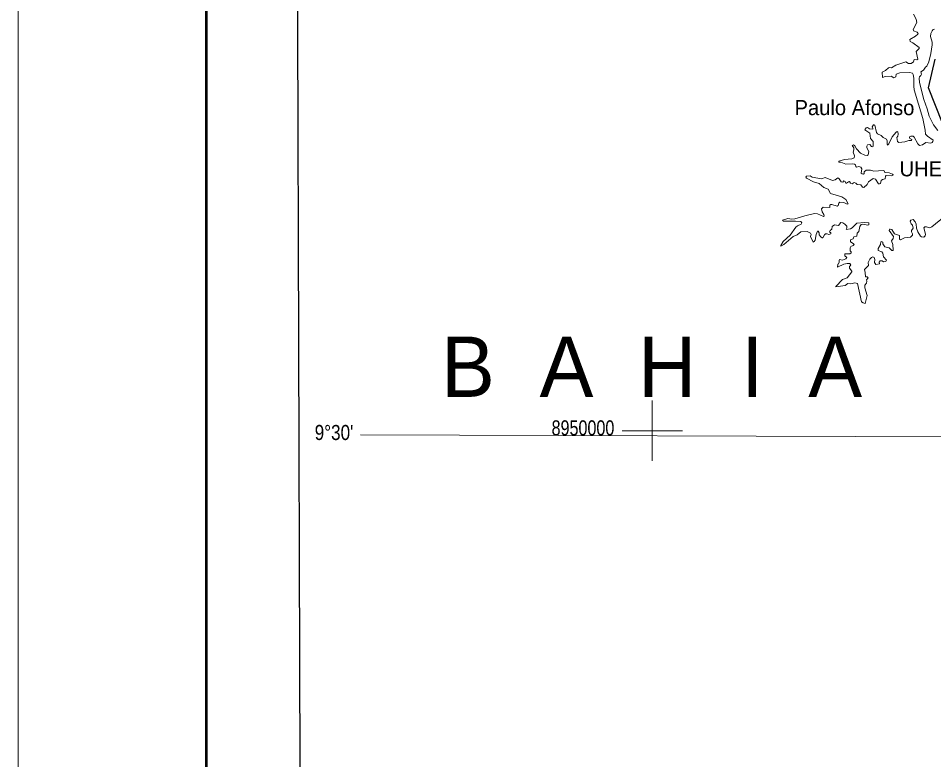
# Model space of a CAD drawing. Extents: x 553962 to 842807, y 8883888 to 9032388.
# Drawn here: x 553962 to 584337, y 8939083 to 8963682 of the extents above; entities that cross this region are included whole.
import ezdxf
from ezdxf.enums import TextEntityAlignment as Align

# ---------------------------------------------------------------- set-up
doc = ezdxf.new("R2010")
doc.units = 0
doc.header["$LTSCALE"] = 150
for name, color, linetype, lineweight in [('1', 7, 'Continuous', 13), ('2', 7, 'Continuous', 13), ('21', 7, 'Continuous', 25), ('25', 7, 'Continuous', 13), ('3', 7, 'Continuous', 13)]:
    doc.layers.add(name, color=color, linetype=linetype, lineweight=lineweight)
for name, color, linetype in [('41', 7, 'Continuous'), ('42', 7, 'Continuous'), ('46', 7, 'Continuous'), ('47', 7, 'Continuous')]:
    doc.layers.add(name, color=color, linetype=linetype)

msp = doc.modelspace()

# ---------------------------------------------------------------- linework, layer by layer
at = {"layer": '1'}
msp.add_line((565315.3, 8949866.8), (791497.7, 8949052.2), dxfattribs=at)
at = {"layer": '2'}
for p, q in [((575000, 8949000), (575000, 8951000)), ((574000, 8950000), (576000, 8950000))]:
    msp.add_line(p, q, dxfattribs=at)
at = {"layer": '21'}
msp.add_lwpolyline([(584626.8, 8960201.4), (584162.8, 8961372.1), (584384.7, 8962320.7)], dxfattribs=at)
at = {"layer": '25'}
for points in [[(582299.4, 8960082.5), (582339.6, 8960143.8), (582362.8, 8960152.2), (582381.9, 8960139.6), (582443.6, 8959893.3), (582477.6, 8959853), (582596.3, 8959797.7), (582656.1, 8959725.5), (582771.8, 8959670.2), (582795.6, 8959619.4), (582792, 8959510.9), (582809, 8959470.7), (582851.4, 8959515.1), (582957.8, 8959753.2), (583089.5, 8959901.9), (583125.3, 8959922.9), (583148.8, 8959914.2), (583159.4, 8959833.8), (583144.6, 8959774.5), (583108.6, 8959723.3), (583108.6, 8959723.3), (583138.3, 8959595.9), (583184.5, 8959559.9), (583382, 8959578.8), (583514.4, 8959627.7), (583603.4, 8959628), (583607.5, 8959661.8), (583550.2, 8959691.6), (583531.3, 8959731.8), (583541.6, 8959757), (583580.3, 8959774.3), (583651.7, 8959765.9), (583684, 8959740.2), (583809.5, 8959521.5), (583862.6, 8959466.3), (583962.4, 8959487.6), (584070.6, 8959557.6), (584244.7, 8959542.8), (584281, 8959557.7), (584312.8, 8959595.8), (584315, 8959638.2), (584126, 8959774.3), (584064.3, 8959836.4), (584055.9, 8959969.5), (583979.3, 8960356.6), (583690.5, 8961308.2), (583675.7, 8961427), (583679.9, 8961694.8), (583656.7, 8961812.9), (583631.9, 8961861.4), (583535.2, 8961883.6), (583208.6, 8961873.1), (583093.8, 8961826.3), (583082.9, 8961741.4), (583013.1, 8961707.5), (582923.6, 8961760.4), (582724.2, 8961752), (582642.1, 8961718.4), (582632.6, 8961889.8), (582741.2, 8961953.9), (582832.4, 8962038.7), (582866.3, 8962051.4), (582940.9, 8962038.9), (583076.4, 8962125.7), (583410.3, 8962234), (583497.2, 8962176.9), (583584.3, 8962176.9), (583662.8, 8962238.5), (583692.8, 8962310.5), (583781.6, 8962306.4), (583807.2, 8962323.5), (583752.2, 8962580.2), (583853.2, 8962685.6), (583854, 8962716.3), (583639.8, 8962873.4), (583552.7, 8962911.8), (583548.2, 8962977.4), (583737.5, 8963086.2), (583815.2, 8963159.7), (583820, 8963181), (583784.2, 8963226), (583667.3, 8963264.5), (583654.7, 8963312.4), (583773.3, 8963547.2), (583756.3, 8963657.4), (583667.3, 8963822.9)], [(582299.4, 8960082.5), (582339.6, 8960143.8), (582362.8, 8960152.2), (582381.9, 8960139.6), (582443.6, 8959893.3), (582477.6, 8959853), (582596.3, 8959797.7), (582656.1, 8959725.5), (582771.8, 8959670.2), (582795.6, 8959619.4), (582792, 8959510.9), (582809, 8959470.7), (582851.4, 8959515.1), (582957.8, 8959753.2), (583089.5, 8959901.9), (583125.3, 8959922.9), (583148.8, 8959914.2), (583159.4, 8959833.8), (583144.6, 8959774.5), (583108.6, 8959723.3), (583108.6, 8959723.3), (583138.3, 8959595.9), (583184.5, 8959559.9), (583382, 8959578.8), (583514.4, 8959627.7), (583603.4, 8959628), (583607.5, 8959661.8), (583550.2, 8959691.6), (583531.3, 8959731.8), (583541.6, 8959757), (583580.3, 8959774.3), (583651.7, 8959765.9), (583684, 8959740.2), (583809.5, 8959521.5), (583862.6, 8959466.3), (583962.4, 8959487.6), (584070.6, 8959557.6), (584244.7, 8959542.8), (584281, 8959557.7), (584312.8, 8959595.8), (584315, 8959638.2), (584126, 8959774.3), (584064.3, 8959836.4), (584055.9, 8959969.5), (583979.3, 8960356.6), (583690.5, 8961308.2), (583675.7, 8961427), (583679.9, 8961694.8), (583656.7, 8961812.9), (583631.9, 8961861.4), (583535.2, 8961883.6), (583208.6, 8961873.1), (583093.8, 8961826.3), (583082.9, 8961741.4), (583013.1, 8961707.5), (582923.6, 8961760.4), (582724.2, 8961752), (582642.1, 8961718.4), (582632.6, 8961889.8), (582741.2, 8961953.9), (582832.4, 8962038.7), (582866.3, 8962051.4), (582940.9, 8962038.9), (583076.4, 8962125.7), (583410.3, 8962234), (583497.2, 8962176.9), (583584.3, 8962176.9), (583662.8, 8962238.5), (583692.8, 8962310.5), (583781.6, 8962306.4), (583807.2, 8962323.5), (583752.2, 8962580.2), (583853.2, 8962685.6), (583854, 8962716.3), (583639.8, 8962873.4), (583552.7, 8962911.8), (583548.2, 8962977.4), (583737.5, 8963086.2), (583815.2, 8963159.7), (583820, 8963181), (583784.2, 8963226), (583667.3, 8963264.5), (583654.7, 8963312.4), (583773.3, 8963547.2), (583756.3, 8963657.4), (583667.3, 8963822.9)], [(584367.9, 8963323.8), (584319.4, 8963311.1), (584283.8, 8963267.3), (584244.9, 8963172.8), (584232.2, 8963079.6), (584283.2, 8962892.7), (584283.2, 8962799.2), (584240.7, 8962518.8), (584172.1, 8962236.3), (584113.2, 8962091.9), (584066.4, 8962055.5), (584002.7, 8961956), (583913.8, 8961907.2), (583936.8, 8961830.6), (583913.5, 8961781.7), (583866.6, 8961740.8), (583856.2, 8961694.6), (583869, 8961554.4), (584009.2, 8960993.4), (584121.2, 8960674.7), (584187.7, 8960432.6), (584325.6, 8960152.6), (584476.5, 8959954.9)], [(584367.9, 8963323.8), (584319.4, 8963311.1), (584283.8, 8963267.3), (584244.9, 8963172.8), (584232.2, 8963079.6), (584283.2, 8962892.7), (584283.2, 8962799.2), (584240.7, 8962518.8), (584172.1, 8962236.3), (584113.2, 8962091.9), (584066.4, 8962055.5), (584002.7, 8961956), (583913.8, 8961907.2), (583936.8, 8961830.6), (583913.5, 8961781.7), (583866.6, 8961740.8), (583856.2, 8961694.6), (583869, 8961554.4), (584009.2, 8960993.4), (584121.2, 8960674.7), (584187.7, 8960432.6), (584325.6, 8960152.6), (584476.5, 8959954.9)], [(580099.6, 8958407.9), (580098.5, 8958410.3), (580113.2, 8958444.3), (580235.9, 8958453.9), (580303, 8958410.4), (580612.5, 8958359.6), (580740.2, 8958401.9), (580973.9, 8958304.4), (581064.7, 8958323.4), (581156.5, 8958384.9), (581203.2, 8958359.3), (581270.9, 8958257.8), (581319.8, 8958245), (581360.2, 8958291.4), (581400.5, 8958268.1), (581420.4, 8958210.8), (581447.3, 8958208.8), (581504.7, 8958259.6), (581539.6, 8958263.8), (581539.6, 8958263.8), (581578.9, 8958209), (581627.9, 8958191.9), (581696, 8958236.1), (581748.9, 8958212.8), (581799.4, 8958164.3), (581920, 8958154), (581978.5, 8958081.4), (582019.4, 8958072.8), (582127.2, 8958170.8), (582178.1, 8958253.3), (582332.9, 8958361.5), (582401, 8958344.6), (582505.1, 8958189.8), (582543.4, 8958185.4), (582568.8, 8958204.3), (582596.6, 8958300), (582641.2, 8958331.9), (582721.7, 8958357.6), (582732.5, 8958448.5), (582755.7, 8958467.7), (582953.2, 8958455.2), (582983.1, 8958470.1), (582989.4, 8958491.2), (582974.4, 8958510.4), (582859.9, 8958554.9), (582719.7, 8958570.1), (582696.2, 8958625.2), (582656.2, 8958635.6), (582353.6, 8958614.5), (582235.7, 8958646.3), (582095.5, 8958639.9), (582031.7, 8958591.2), (582027, 8958531.6), (582005.7, 8958514.7), (581967.3, 8958516.9), (581933.7, 8958544.9), (581955, 8958692.5), (581922.9, 8958748.3), (581848.8, 8958761), (581780.6, 8958746.3), (581757.5, 8958761.1), (581738.2, 8958822.6), (581712.6, 8958841.7), (581627.9, 8958854.5), (581424.2, 8958839.7), (581251.8, 8958907.5), (581194.6, 8958907.9), (581190.6, 8958937.3), (581381.2, 8958994.6), (581615.1, 8959015.9), (581699.9, 8959047.7), (581708.6, 8959122.1), (581659.8, 8959239), (581692.1, 8959315.5), (581691.6, 8959378.9), (581634.5, 8959460), (581670.4, 8959485.2), (581717.2, 8959451.2), (581774.6, 8959353.5), (581908.3, 8959202.9), (582046.5, 8959141.3), (582129.4, 8959128.6), (582167.3, 8959147.5), (582188.6, 8959260.2), (582118.7, 8959385.4), (582116.5, 8959440.5), (582142.1, 8959487.4), (582214.1, 8959495.9), (582278, 8959423.9), (582316.1, 8959415.5), (582331, 8959439.1), (582330.8, 8959589.7), (582237.6, 8959695.7), (582220.4, 8959865.6), (582050.7, 8959980.4), (582091.2, 8960052.6), (582141.7, 8960063.2), (582208.1, 8960016.5), (582315.9, 8960001.7), (582322.5, 8960029), (582299.4, 8960082.5)], [(580099.6, 8958407.9), (580098.5, 8958410.3), (580113.2, 8958444.3), (580235.9, 8958453.9), (580303, 8958410.4), (580612.5, 8958359.6), (580740.2, 8958401.9), (580973.9, 8958304.4), (581064.7, 8958323.4), (581156.5, 8958384.9), (581203.2, 8958359.3), (581270.9, 8958257.8), (581319.8, 8958245), (581360.2, 8958291.4), (581400.5, 8958268.1), (581420.4, 8958210.8), (581447.3, 8958208.8), (581504.7, 8958259.6), (581539.6, 8958263.8), (581539.6, 8958263.8), (581578.9, 8958209), (581627.9, 8958191.9), (581696, 8958236.1), (581748.9, 8958212.8), (581799.4, 8958164.3), (581920, 8958154), (581978.5, 8958081.4), (582019.4, 8958072.8), (582127.2, 8958170.8), (582178.1, 8958253.3), (582332.9, 8958361.5), (582401, 8958344.6), (582505.1, 8958189.8), (582543.4, 8958185.4), (582568.8, 8958204.3), (582596.6, 8958300), (582641.2, 8958331.9), (582721.7, 8958357.6), (582732.5, 8958448.5), (582755.7, 8958467.7), (582953.2, 8958455.2), (582983.1, 8958470.1), (582989.4, 8958491.2), (582974.4, 8958510.4), (582859.9, 8958554.9), (582719.7, 8958570.1), (582696.2, 8958625.2), (582656.2, 8958635.6), (582353.6, 8958614.5), (582235.7, 8958646.3), (582095.5, 8958639.9), (582031.7, 8958591.2), (582027, 8958531.6), (582005.7, 8958514.7), (581967.3, 8958516.9), (581933.7, 8958544.9), (581955, 8958692.5), (581922.9, 8958748.3), (581848.8, 8958761), (581780.6, 8958746.3), (581757.5, 8958761.1), (581738.2, 8958822.6), (581712.6, 8958841.7), (581627.9, 8958854.5), (581424.2, 8958839.7), (581251.8, 8958907.5), (581194.6, 8958907.9), (581190.6, 8958937.3), (581381.2, 8958994.6), (581615.1, 8959015.9), (581699.9, 8959047.7), (581708.6, 8959122.1), (581659.8, 8959239), (581692.1, 8959315.5), (581691.6, 8959378.9), (581634.5, 8959460), (581670.4, 8959485.2), (581717.2, 8959451.2), (581774.6, 8959353.5), (581908.3, 8959202.9), (582046.5, 8959141.3), (582129.4, 8959128.6), (582167.3, 8959147.5), (582188.6, 8959260.2), (582118.7, 8959385.4), (582116.5, 8959440.5), (582142.1, 8959487.4), (582214.1, 8959495.9), (582278, 8959423.9), (582316.1, 8959415.5), (582331, 8959439.1), (582330.8, 8959589.7), (582237.6, 8959695.7), (582220.4, 8959865.6), (582050.7, 8959980.4), (582091.2, 8960052.6), (582141.7, 8960063.2), (582208.1, 8960016.5), (582315.9, 8960001.7), (582322.5, 8960029), (582299.4, 8960082.5)], [(579330.4, 8956970.9), (579320.1, 8956982.2), (579494.9, 8957040.3), (579635.1, 8957021.3), (579729, 8957025.6), (580056.8, 8957131.9), (580383.3, 8957210.3), (580477.4, 8957190.9), (580682.8, 8957104.2), (580701.6, 8957122.8), (580693.2, 8957169.7), (580640, 8957259.4), (580619.2, 8957363.6), (580667.8, 8957416.2), (580886.3, 8957410), (580890.9, 8957486.6), (580919.1, 8957507.7), (580955.2, 8957509.6), (581130.8, 8957450.5), (581162.8, 8957476.1), (581188.5, 8957544.2), (581224.5, 8957577.8), (581357.9, 8957571.4), (581466.2, 8957520.6), (581496, 8957526.9), (581421.8, 8957673.3), (581289.9, 8957760.6), (580910.1, 8957870.9), (580835.5, 8958013.2), (580692.5, 8958073.2), (580540.2, 8958198), (580349.1, 8958255.5), (580111.4, 8958382.8), (580099.6, 8958407.9)], [(579330.4, 8956970.9), (579320.1, 8956982.2), (579494.9, 8957040.3), (579635.1, 8957021.3), (579729, 8957025.6), (580056.8, 8957131.9), (580383.3, 8957210.3), (580477.4, 8957190.9), (580682.8, 8957104.2), (580701.6, 8957122.8), (580693.2, 8957169.7), (580640, 8957259.4), (580619.2, 8957363.6), (580667.8, 8957416.2), (580886.3, 8957410), (580890.9, 8957486.6), (580919.1, 8957507.7), (580955.2, 8957509.6), (581130.8, 8957450.5), (581162.8, 8957476.1), (581188.5, 8957544.2), (581224.5, 8957577.8), (581357.9, 8957571.4), (581466.2, 8957520.6), (581496, 8957526.9), (581421.8, 8957673.3), (581289.9, 8957760.6), (580910.1, 8957870.9), (580835.5, 8958013.2), (580692.5, 8958073.2), (580540.2, 8958198), (580349.1, 8958255.5), (580111.4, 8958382.8), (580099.6, 8958407.9)], [(584696, 8957104.7), (584274.9, 8956764.4), (584197.5, 8956726), (584094.1, 8956768.4), (584038.7, 8956757.6), (584011.4, 8956727.3), (584062.2, 8956515.4), (584055.8, 8956462.4), (584011.2, 8956420.2), (583928.7, 8956432.8), (583896.6, 8956454.1), (583805.3, 8956596.4), (583767, 8956723.9), (583756.3, 8956851.3), (583724.4, 8956925.6), (583660.8, 8957002.1), (583580.2, 8956987.2), (583561.1, 8956946.9), (583586.5, 8956859.9), (583628.7, 8956817.4), (583660.7, 8956715.7), (583603.4, 8956642.9), (583599.3, 8956600.4), (583635.2, 8956528.2), (583628.9, 8956482), (583569.2, 8956422.2), (583365.5, 8956403), (583235.8, 8956333.2), (583204.2, 8956354.3), (583197.6, 8956473.1), (583036.3, 8956532.7), (582944.7, 8956675), (582889.9, 8956689.8), (582866.4, 8956681.3), (582857.8, 8956639.1), (583000.1, 8956445.4), (583000.1, 8956445.4), (582995.8, 8956371.3), (582932.2, 8956297.6), (582978.9, 8956171.6), (582991.4, 8955993), (582976.7, 8955976.2), (582947.1, 8955976.2), (582856.3, 8956071.3), (582711.3, 8956099.4), (582652.2, 8956196.2), (582645.2, 8956252.4), (582607.4, 8956273.4), (582579.8, 8956265), (582570.9, 8956175.6), (582492.5, 8956044.1), (582498.8, 8955974.4), (582613.2, 8955937.9), (582649.7, 8955884.6), (582675.3, 8955763.5), (582766.3, 8955661.9), (582751.6, 8955613.2), (582671.6, 8955604.4), (582632.4, 8955638.4), (582558.3, 8955632), (582532.9, 8955594), (582534.7, 8955540.7), (582411.8, 8955511), (582367.2, 8955576.8), (582379.8, 8955678.5), (582358.6, 8955744.6), (582321.7, 8955763.6), (582269.6, 8955750.9), (582214, 8955691.2), (582157.1, 8955581.8), (582171.5, 8955478.9), (582040.1, 8955351.6), (582061.2, 8955249.4), (582072.2, 8955107.3), (582129.2, 8955100.8), (582163, 8955071.2), (582108.2, 8955005.5), (582120.6, 8954960.7), (582103.7, 8954893.1), (582052.8, 8954828.8), (582057, 8954744.1), (582129.2, 8954489.4), (582066.7, 8954223.6)], [(584696, 8957104.7), (584274.9, 8956764.4), (584197.5, 8956726), (584094.1, 8956768.4), (584038.7, 8956757.6), (584011.4, 8956727.3), (584062.2, 8956515.4), (584055.8, 8956462.4), (584011.2, 8956420.2), (583928.7, 8956432.8), (583896.6, 8956454.1), (583805.3, 8956596.4), (583767, 8956723.9), (583756.3, 8956851.3), (583724.4, 8956925.6), (583660.8, 8957002.1), (583580.2, 8956987.2), (583561.1, 8956946.9), (583586.5, 8956859.9), (583628.7, 8956817.4), (583660.7, 8956715.7), (583603.4, 8956642.9), (583599.3, 8956600.4), (583635.2, 8956528.2), (583628.9, 8956482), (583569.2, 8956422.2), (583365.5, 8956403), (583235.8, 8956333.2), (583204.2, 8956354.3), (583197.6, 8956473.1), (583036.3, 8956532.7), (582944.7, 8956675), (582889.9, 8956689.8), (582866.4, 8956681.3), (582857.8, 8956639.1), (583000.1, 8956445.4), (583000.1, 8956445.4), (582995.8, 8956371.3), (582932.2, 8956297.6), (582978.9, 8956171.6), (582991.4, 8955993), (582976.7, 8955976.2), (582947.1, 8955976.2), (582856.3, 8956071.3), (582711.3, 8956099.4), (582652.2, 8956196.2), (582645.2, 8956252.4), (582607.4, 8956273.4), (582579.8, 8956265), (582570.9, 8956175.6), (582492.5, 8956044.1), (582498.8, 8955974.4), (582613.2, 8955937.9), (582649.7, 8955884.6), (582675.3, 8955763.5), (582766.3, 8955661.9), (582751.6, 8955613.2), (582671.6, 8955604.4), (582632.4, 8955638.4), (582558.3, 8955632), (582532.9, 8955594), (582534.7, 8955540.7), (582411.8, 8955511), (582367.2, 8955576.8), (582379.8, 8955678.5), (582358.6, 8955744.6), (582321.7, 8955763.6), (582269.6, 8955750.9), (582214, 8955691.2), (582157.1, 8955581.8), (582171.5, 8955478.9), (582040.1, 8955351.6), (582061.2, 8955249.4), (582072.2, 8955107.3), (582129.2, 8955100.8), (582163, 8955071.2), (582108.2, 8955005.5), (582120.6, 8954960.7), (582103.7, 8954893.1), (582052.8, 8954828.8), (582057, 8954744.1), (582129.2, 8954489.4), (582066.7, 8954223.6)], [(579269.2, 8956128.5), (579267.5, 8956147.6), (579346.5, 8956275.5), (579569.6, 8956488.2), (579763, 8956751.6), (579818, 8956796.1), (579936.8, 8956853.3), (579964.5, 8956895.9), (579931, 8956942.9), (579750.3, 8956955.4), (579346.5, 8956953.4), (579330.4, 8956970.9)], [(579269.2, 8956128.5), (579267.5, 8956147.6), (579346.5, 8956275.5), (579569.6, 8956488.2), (579763, 8956751.6), (579818, 8956796.1), (579936.8, 8956853.3), (579964.5, 8956895.9), (579931, 8956942.9), (579750.3, 8956955.4), (579346.5, 8956953.4), (579330.4, 8956970.9)], [(581087.4, 8954777.9), (581086.2, 8954783.2), (581309.3, 8955015.9), (581466.6, 8955071.4), (581619.3, 8955264.8), (581619.2, 8955294.3), (581547.2, 8955390.1), (581547.2, 8955446.9), (581591.7, 8955496), (581559.6, 8955544.9), (581466.4, 8955547), (581352.5, 8955521.7), (581145.7, 8955426.2), (581160.6, 8955521.3), (581179.9, 8955534.8), (581200.8, 8955593.5), (581201, 8955657.4), (581215.8, 8955674.4), (581310.1, 8955657.7), (581421.9, 8955695.9), (581449.3, 8955742.7), (581390.1, 8955804.1), (581390.2, 8955865.7), (581551.4, 8955867.9), (581597.9, 8955895.3), (581593.8, 8955933.6), (581560, 8955969.8), (581562.1, 8956061.3), (581585.5, 8956114.1), (581661.8, 8956146.1), (581693.6, 8956177.9), (581665.8, 8956214.1), (581581.2, 8956260.8), (581578.8, 8956332.5), (581666, 8956369.2), (581685.3, 8956432.7), (581787.1, 8956452), (581795.2, 8956554.8), (581857.1, 8956604.5), (581891.2, 8956774.6), (581933.5, 8956840.4), (581969.4, 8956847.3), (582150.4, 8956819.5), (582182.3, 8956832.5), (582180, 8956896), (582043.8, 8956902.2), (581783.2, 8956880.5), (581783.2, 8956880.5), (581630, 8956728.1), (581572.6, 8956696.3), (581434.7, 8956673.2), (581455.8, 8956719.8), (581453.6, 8956783.3), (581388, 8956855.3), (581326.2, 8956893.7), (581251.9, 8956904.3), (581175.2, 8956811), (581041.6, 8956834.2), (580969.4, 8956772.7), (580958.6, 8956687.6), (580901.5, 8956645.2), (580882.6, 8956601.5), (580922.5, 8956566.6), (580922.4, 8956530.5), (580856.8, 8956505.1), (580801.5, 8956530.5), (580744, 8956530.4), (580708.6, 8956501.7), (580663.4, 8956403.2), (580631.7, 8956403.2), (580586.8, 8956433.1), (580540.2, 8956494.7), (580531.6, 8956562.6), (580499.8, 8956617.5), (580482.8, 8956619.5), (580431.9, 8956511.2), (580408.5, 8956324.5), (580372.3, 8956271.5), (580340.8, 8956252.5), (580251.5, 8956443.2), (580274.6, 8956509.1), (580253.4, 8956549.5), (580136.6, 8956613.3), (579924, 8956592), (579805, 8956498.6), (579677.6, 8956436.9), (579359.2, 8956171.6), (579269.9, 8956121.1), (579269.2, 8956128.5)], [(581087.4, 8954777.9), (581086.2, 8954783.2), (581309.3, 8955015.9), (581466.6, 8955071.4), (581619.3, 8955264.8), (581619.2, 8955294.3), (581547.2, 8955390.1), (581547.2, 8955446.9), (581591.7, 8955496), (581559.6, 8955544.9), (581466.4, 8955547), (581352.5, 8955521.7), (581145.7, 8955426.2), (581160.6, 8955521.3), (581179.9, 8955534.8), (581200.8, 8955593.5), (581201, 8955657.4), (581215.8, 8955674.4), (581310.1, 8955657.7), (581421.9, 8955695.9), (581449.3, 8955742.7), (581390.1, 8955804.1), (581390.2, 8955865.7), (581551.4, 8955867.9), (581597.9, 8955895.3), (581593.8, 8955933.6), (581560, 8955969.8), (581562.1, 8956061.3), (581585.5, 8956114.1), (581661.8, 8956146.1), (581693.6, 8956177.9), (581665.8, 8956214.1), (581581.2, 8956260.8), (581578.8, 8956332.5), (581666, 8956369.2), (581685.3, 8956432.7), (581787.1, 8956452), (581795.2, 8956554.8), (581857.1, 8956604.5), (581891.2, 8956774.6), (581933.5, 8956840.4), (581969.4, 8956847.3), (582150.4, 8956819.5), (582182.3, 8956832.5), (582180, 8956896), (582043.8, 8956902.2), (581783.2, 8956880.5), (581783.2, 8956880.5), (581630, 8956728.1), (581572.6, 8956696.3), (581434.7, 8956673.2), (581455.8, 8956719.8), (581453.6, 8956783.3), (581388, 8956855.3), (581326.2, 8956893.7), (581251.9, 8956904.3), (581175.2, 8956811), (581041.6, 8956834.2), (580969.4, 8956772.7), (580958.6, 8956687.6), (580901.5, 8956645.2), (580882.6, 8956601.5), (580922.5, 8956566.6), (580922.4, 8956530.5), (580856.8, 8956505.1), (580801.5, 8956530.5), (580744, 8956530.4), (580708.6, 8956501.7), (580663.4, 8956403.2), (580631.7, 8956403.2), (580586.8, 8956433.1), (580540.2, 8956494.7), (580531.6, 8956562.6), (580499.8, 8956617.5), (580482.8, 8956619.5), (580431.9, 8956511.2), (580408.5, 8956324.5), (580372.3, 8956271.5), (580340.8, 8956252.5), (580251.5, 8956443.2), (580274.6, 8956509.1), (580253.4, 8956549.5), (580136.6, 8956613.3), (579924, 8956592), (579805, 8956498.6), (579677.6, 8956436.9), (579359.2, 8956171.6), (579269.9, 8956121.1), (579269.2, 8956128.5)], [(582066.7, 8954223.6), (582065.2, 8954217.4), (581995.8, 8954238.9), (581939.2, 8954279.2), (581803.6, 8954880.3), (581719.8, 8954905.5), (581585.7, 8954873.7), (581483.7, 8954877.8), (581402.7, 8954812.1), (581089.5, 8954768.8), (581087.4, 8954777.9)], [(582066.7, 8954223.6), (582065.2, 8954217.4), (581995.8, 8954238.9), (581939.2, 8954279.2), (581803.6, 8954880.3), (581719.8, 8954905.5), (581585.7, 8954873.7), (581483.7, 8954877.8), (581402.7, 8954812.1), (581089.5, 8954768.8), (581087.4, 8954777.9)]]:
    msp.add_lwpolyline(points, dxfattribs=at)
at = {"layer": '3'}
msp.add_lwpolyline([(842807.3, 9032387.8), (842807.3, 8883887.8), (553961.7, 8883887.8), (553961.7, 9032387.8)], close=True, dxfattribs=at)
at = {"layer": '3', "lineweight": 53}
msp.add_lwpolyline([(840307.3, 9029887.8), (840307.3, 8886387.8), (560211.7, 8886387.8), (560211.7, 9029887.8)], close=True, dxfattribs=at)
at = {"layer": '3', "lineweight": 25}
msp.add_lwpolyline([(563033.9, 9026438.8), (793061.1, 9026438.8), (793495.6, 8889836.8), (563468.3, 8889836.8)], close=True, dxfattribs=at)

# ---------------------------------------------------------------- texts
at = {"layer": '41'}
msp.add_text('Paulo Afonso', height=500, dxfattribs=at).set_placement((581707.6, 8960468.8), align=Align.CENTER)
at = {"layer": '42'}
msp.add_text('UHE PA IV', height=500, dxfattribs=at).set_placement((584857.3, 8958438.7), align=Align.CENTER)
msp.add_text('B  A  H  I  A', height=2000, dxfattribs=at).set_placement((567989.8, 8951121.2))
at = {"layer": '46', "width": 0.85}
msp.add_text("9°30'", height=500, dxfattribs=at).set_placement((564438.8, 8949689.6), align=Align.CENTER)
at = {"layer": '47', "width": 0.8}
msp.add_text('8950000', height=500, dxfattribs=at).set_placement((572698.6, 8949843), align=Align.CENTER)

doc.saveas('drawing.dxf')
